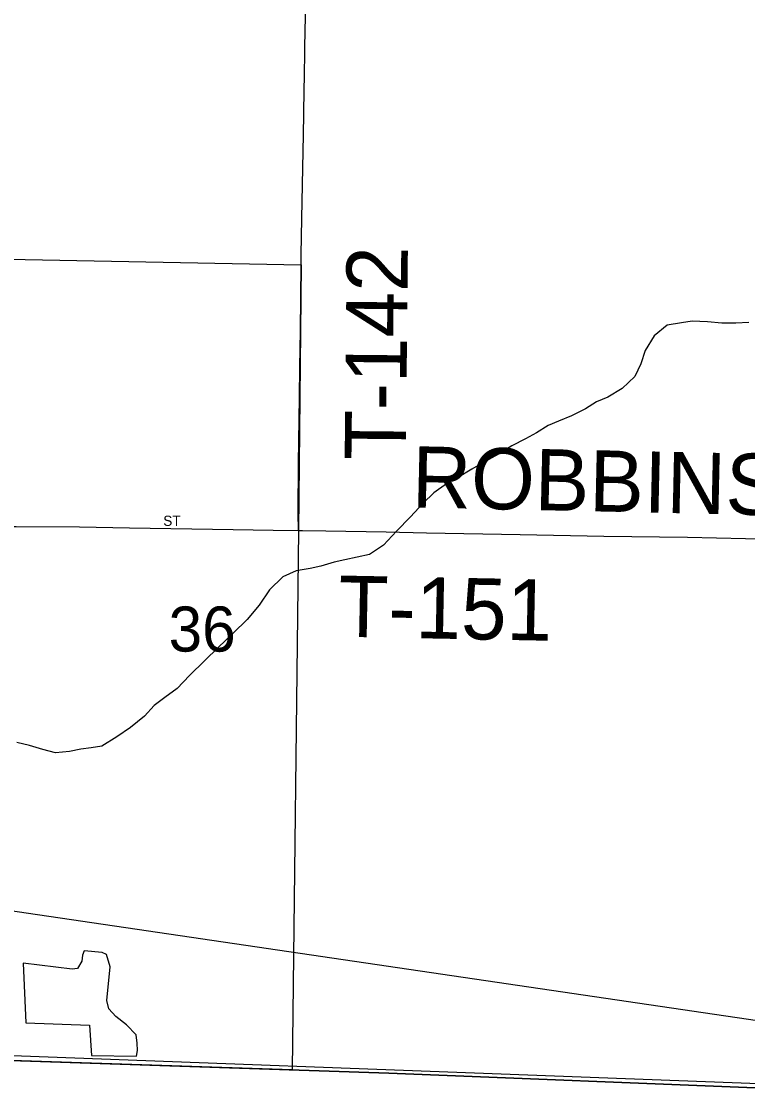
# Model space of a CAD drawing. Extents: x 1443599 to 1910620, y 1028088 to 1361369.
# Drawn here: x 1679403 to 1682963, y 1154990 to 1160251 of the extents above; entities that cross this region are included whole.
import ezdxf

# ---------------------------------------------------------------- set-up
doc = ezdxf.new("R2010")
doc.units = 0
for name, color, linetype in [('GM_X_Adjacent_County', 7, 'Continuous'), ('GM_X_City_Street', 7, 'Continuous'), ('GM_X_City_Street_Text', 7, 'Continuous'), ('GM_X_Corporation', 7, 'Continuous'), ('GM_X_County', 7, 'Continuous'), ('GM_X_Minor_Lake', 7, 'Continuous'), ('GM_X_Minor_River', 7, 'Continuous'), ('GM_X_Rail_Line', 7, 'Continuous'), ('GM_X_Section', 7, 'Continuous'), ('GM_X_Section_Text', 7, 'Continuous'), ('GM_X_Township', 7, 'Continuous'), ('GM_X_Township_Road', 7, 'Continuous'), ('GM_X_Township_Road_Text', 7, 'Continuous')]:
    doc.layers.add(name, color=color, linetype=linetype)

msp = doc.modelspace()

# ---------------------------------------------------------------- linework, layer by layer
at = {"layer": 'GM_X_Adjacent_County'}
msp.add_lwpolyline([(1658061.8, 1155840.1), (1658626.2, 1155812.7), (1660715.6, 1155753.3), (1662207.7, 1155721.8), (1662223.2, 1155721.4), (1663663.8, 1155691), (1665422.8, 1155665.7), (1666014.4, 1155680), (1667502.8, 1155634.4), (1668273.2, 1155610.8), (1669238.7, 1155599.2), (1670479, 1155544.6), (1672776.2, 1155425.2), (1673256.5, 1155400.2), (1674889.7, 1155358.7), (1675432.5, 1155320.6), (1676167.1, 1155269.1), (1677665.6, 1155235.4), (1678018.8, 1155227.5), (1678763.6, 1155175.7), (1681204.2, 1155094.6), (1683083.1, 1155019.2)], dxfattribs=at)
at = {"layer": 'GM_X_City_Street'}
msp.add_lwpolyline([(1678883.7, 1157782.2), (1678951.8, 1157780.9), (1679197.2, 1157776.3), (1679262.6, 1157775.7), (1679377, 1157774.9), (1679687.6, 1157772.7), (1679933.2, 1157767.8), (1680440.5, 1157760.9), (1680637, 1157756.6), (1680761.1, 1157755.2)], dxfattribs=at)
at = {"layer": 'GM_X_Corporation'}
msp.add_lwpolyline([(1675436.4, 1155294.9), (1675513.9, 1157696.2), (1676322.4, 1157724.4), (1676790, 1157703.9), (1676825, 1159146.9), (1677600.9, 1159130.4), (1677775.5, 1159124.5), (1678150.9, 1159107.9), (1680775.2, 1159057.9), (1680761.1, 1157755.2), (1680730, 1155110.3), (1678763.6, 1155175.7), (1678018.8, 1155227.5), (1676169, 1155269)], close=True, dxfattribs=at)
at = {"layer": 'GM_X_County'}
msp.add_lwpolyline([(1683083.1, 1155019.2), (1681204.2, 1155094.6), (1678763.6, 1155175.7), (1678018.8, 1155227.5), (1677665.6, 1155235.4), (1676167.1, 1155269.1), (1675432.5, 1155320.6), (1674889.7, 1155358.7), (1673256.5, 1155400.2), (1672776.2, 1155425.2), (1670479, 1155544.6), (1669238.7, 1155599.2), (1668273.2, 1155610.8), (1667502.8, 1155634.4), (1666014.4, 1155680), (1665422.8, 1155665.7), (1663663.8, 1155691), (1662223.2, 1155721.4), (1662207.7, 1155721.8), (1660715.6, 1155753.3), (1658626.2, 1155812.7), (1658061.8, 1155840.1)], dxfattribs=at)
at = {"layer": 'GM_X_Minor_Lake'}
msp.add_line((1679411.4, 1155633.8), (1679424.7, 1155340.9), dxfattribs=at)
msp.add_lwpolyline([(1679424.7, 1155340.9), (1679736.5, 1155329.6), (1679747.1, 1155181), (1679967.1, 1155177.8), (1679971.7, 1155205.8), (1679970.5, 1155241.9), (1679965.5, 1155282.1), (1679918.6, 1155331.3), (1679865.5, 1155372.6), (1679832.3, 1155409.5), (1679821.3, 1155451.8), (1679839, 1155615.7), (1679820.4, 1155676.3), (1679798.6, 1155686.8), (1679710.8, 1155694.9), (1679702.3, 1155673.1), (1679699.6, 1155643.1), (1679678.8, 1155607.5), (1679652.7, 1155604.1), (1679411.4, 1155633.8)], dxfattribs=at)
at = {"layer": 'GM_X_Minor_River'}
for points in [[(1682969.5, 1158775.9), (1682905.4, 1158772.1), (1682837.3, 1158772.3), (1682767.5, 1158778.7), (1682691.5, 1158781.3), (1682639.2, 1158773), (1682568.8, 1158761.4), (1682505.1, 1158709.4), (1682460.7, 1158638.7), (1682440.6, 1158573.3), (1682410.5, 1158510.2), (1682348.5, 1158452.1), (1682279.1, 1158408.4), (1682222.3, 1158386.2), (1682169.1, 1158351.9), (1682100, 1158318.2), (1682037.1, 1158292.3), (1681986.3, 1158269.9), (1681929.1, 1158233.8), (1681874.2, 1158205.6), (1681807, 1158169.8), (1681741.6, 1158129.9), (1681676.4, 1158094), (1681611.1, 1158056.1), (1681541.7, 1158014.3), (1681486.7, 1157984.1), (1681425.2, 1157940.1), (1681373.5, 1157889.7), (1681311.2, 1157821.7), (1681242.9, 1157751.8), (1681178.7, 1157683.8), (1681109.1, 1157638.1), (1680988.2, 1157612.1), (1680935.8, 1157599.8), (1680871.1, 1157580), (1680818.7, 1157569.7), (1680750.3, 1157558), (1680685.3, 1157528.1), (1680619.1, 1157464.2), (1680568.7, 1157389.8), (1680510.3, 1157319.6), (1680442.1, 1157251.7), (1680367.7, 1157182.1), (1680301.6, 1157118.1), (1680227.1, 1157044.5), (1680167, 1156980.4), (1680105.5, 1156936.4), (1680054.2, 1156898), (1680006.5, 1156845.5)], [(1680006.5, 1156845.5), (1679938.6, 1156789.6), (1679871.1, 1156743.8), (1679797.5, 1156698.2), (1679745.2, 1156689.9), (1679695, 1156683.6), (1679638.6, 1156671.5), (1679570.3, 1156665.8), (1679508.8, 1156681.9), (1679443.5, 1156702.1), (1679379.9, 1156716.3)]]:
    msp.add_lwpolyline(points, dxfattribs=at)
at = {"layer": 'GM_X_Rail_Line'}
msp.add_lwpolyline([(1653131.7, 1159734.3), (1654559.8, 1159532.2), (1656720, 1159206.3), (1661518.7, 1158502.4), (1663430.3, 1158232.7), (1665610.5, 1157902.5), (1670331.1, 1157208.4), (1674785.3, 1156557.2), (1678092.3, 1156076.4), (1685476.1, 1154990)], dxfattribs=at)
at = {"layer": 'GM_X_Section'}
msp.add_lwpolyline([(1678169.2, 1160435.4), (1683444, 1160353.5), (1683440.9, 1160257.5), (1683367.5, 1155028.6), (1678052, 1155228.8)], close=True, dxfattribs=at)
at = {"layer": 'GM_X_Township'}
msp.add_lwpolyline([(1683083.1, 1155019.2), (1681204.2, 1155094.6), (1678763.6, 1155175.7), (1678018.8, 1155227.5), (1677665.6, 1155235.4), (1676167.1, 1155269.1), (1675432.5, 1155320.6), (1674889.7, 1155358.7), (1673256.5, 1155400.2), (1672776.2, 1155425.2), (1670479, 1155544.6), (1669238.7, 1155599.2), (1668273.2, 1155610.8), (1667502.8, 1155634.4), (1666014.4, 1155680), (1665422.8, 1155665.7), (1663663.8, 1155691), (1662223.2, 1155721.4), (1662207.7, 1155721.8), (1660715.6, 1155753.3), (1658626.2, 1155812.7), (1658061.8, 1155840.1)], dxfattribs=at)
at = {"layer": 'GM_X_Township_Road'}
for points in [[(1680775.2, 1159057.9), (1680775.2, 1159106.6), (1680778.2, 1159285.4), (1680781.5, 1159450.2), (1680786.6, 1159697.5), (1680788.4, 1159796.3), (1680788.5, 1159812.7), (1680790.5, 1159993.8), (1680792.1, 1160092.4), (1680792.5, 1160125.2), (1680796.5, 1160277.2), (1680798, 1160371.5), (1680798.5, 1160402.8)], [(1680761.1, 1157755.2), (1680760.7, 1157840.1), (1680761.5, 1158083.3), (1680766.4, 1158409.3), (1680768.4, 1158555.9), (1680771.8, 1158735), (1680775.2, 1159057.9)], [(1680761.1, 1157755.2), (1680781.3, 1157755.1), (1680896.1, 1157754.2), (1681191.5, 1157748.2), (1681388.5, 1157744.4), (1681848.1, 1157736.1), (1682258.4, 1157727), (1682668.9, 1157722.3), (1683095.6, 1157712.9), (1683194, 1157708.8), (1683259.4, 1157702.9), (1683308.1, 1157695.5), (1683372.3, 1157682.1), (1683385.2, 1157678.8)]]:
    msp.add_lwpolyline(points, dxfattribs=at)

# ---------------------------------------------------------------- texts
at = {"layer": 'GM_X_City_Street_Text'}
msp.add_text('ST', height=50, rotation=0, dxfattribs=at).set_placement((1680098.4, 1157778.1))
at = {"layer": 'GM_X_Section_Text'}
msp.add_text('36', height=221, rotation=0, dxfattribs=at).set_placement((1680124.8, 1157161.8))
at = {"layer": 'GM_X_Township_Road_Text'}
for s, rotation, p in [('T-142', 89.4391, (1681287.9, 1158099.2)), ('ROBBINS', 358.7343, (1681315.5, 1157869.1)), ('T-151', 358.8926, (1680954.9, 1157234.9))]:
    msp.add_text(s, height=300, rotation=rotation, dxfattribs=at).set_placement(p)

doc.saveas('drawing.dxf')
